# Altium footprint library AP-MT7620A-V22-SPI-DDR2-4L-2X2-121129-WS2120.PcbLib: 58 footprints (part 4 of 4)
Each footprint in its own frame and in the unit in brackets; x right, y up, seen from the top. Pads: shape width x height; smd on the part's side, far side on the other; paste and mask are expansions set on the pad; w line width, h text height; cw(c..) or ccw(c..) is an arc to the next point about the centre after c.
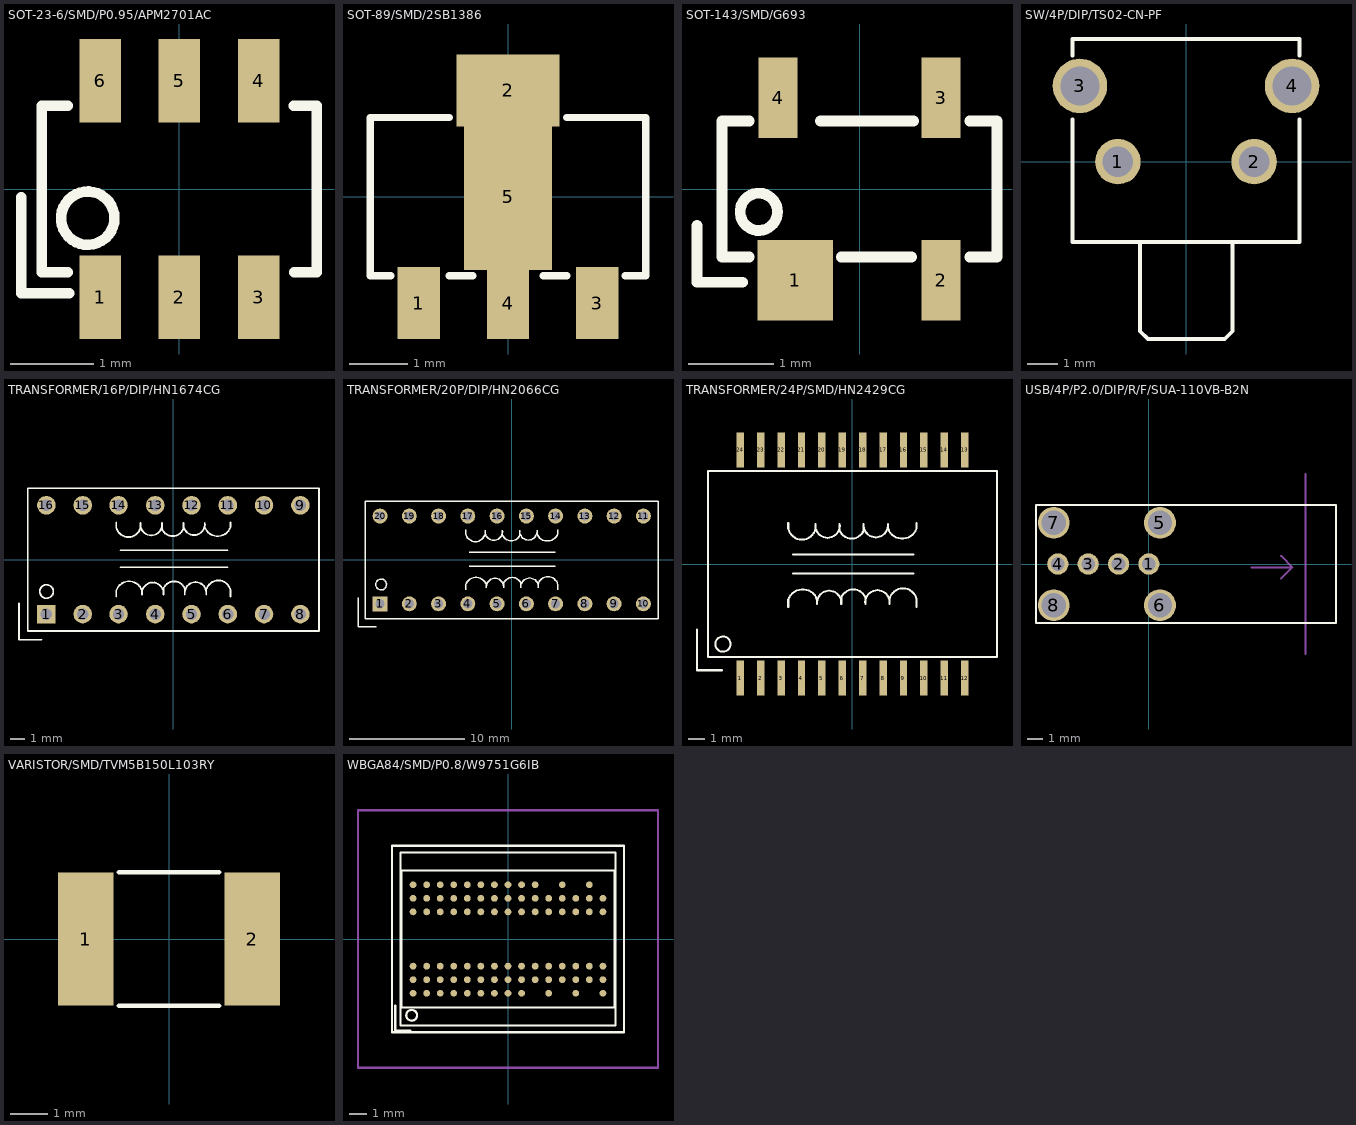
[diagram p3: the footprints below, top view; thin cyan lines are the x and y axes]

## SOT-23-6/SMD/P0.95/APM2701AC [mm]
pads (6):
  rect 0.5x1 smd: 1(-0.95,-1.3) 2(0,-1.3) 3(0.95,-1.3) 4(0.95,1.3) 5(0,1.3) 6(-0.95,1.3)
Top Overlay:
  circle w0.127: c-1.1,-0.35 r0.32
  lines w0.127: -1.9,-0.1 -1.9,-1.25 -1.32,-1.25 ; -1.34,-1 -1.65,-1 -1.65,1 -1.34,1 ; 1.37,1 1.65,1 1.65,-1 1.38,-1

## SOT-89/SMD/2SB1386 [mm]
pads (5):
  rect 0.72x1.225 smd: 1(-1.52,-1.813) 3(1.52,-1.813) 4(0,-1.813)
  rect 1.75x1.225 smd: 2(0,1.813)
  rect 1.5x2.5 smd: 5(0,0)
Top Overlay:
  lines w0.127: -2,-1.35 -2.35,-1.35 -2.35,1.35 -1,1.35 ; -1,-1.35 -0.6,-1.35 ; 0.6,-1.35 1,-1.35 ; 1,1.35 2.35,1.35 2.35,-1.35 2,-1.35

## SOT-143/SMD/G693 [mm]
pads (4):
  rect 0.89x0.95 smd: 1(-0.76,-1.075)
  rect 0.46x0.95 smd: 2(0.96,-1.075) 3(0.96,1.075) 4(-0.96,1.075)
Top Overlay:
  circle w0.127: c-1.187,-0.269 r0.22
  lines w0.127: -1.916,-0.432 -1.916,-1.1 -1.381,-1.1 ; -1.3,-0.8 -1.62,-0.8 -1.62,0.8 -1.3,0.8 ; -0.46,0.8 0.635,0.8 ; -0.216,-0.8 0.611,-0.8 ; 1.3,-0.8 1.62,-0.8 1.62,0.8 1.3,0.8

## SW/4P/DIP/TS02-CN-PF [mm]
pads (4):
  round 1.5 hole 1: 1(-2.25,0) 2(2.25,0)
  round 1.8 hole 1.3: 3(-3.5,2.5) 4(3.5,2.5)
Top Overlay:
  lines w0.127: -3.75,1.4 -3.75,-2.65 3.75,-2.65 3.75,1.4 ; -3.75,3.5 -3.75,4.05 3.75,4.05 3.75,3.5 ; -1.514,-2.677 -1.514,-5.598 -1.26,-5.852 1.28,-5.852 1.534,-5.598 1.534,-2.677

## TRANSFORMER/16P/DIP/HN1674CG [mm]
pads (16):
  rect 1.3x1.3 / inner round 1.3 / far side round 1.3 hole 0.8: 1(-8.9,-3.81)
  round 1.3 hole 0.8: 2(-6.35,-3.81) 3(-3.843,-3.81) 4(-1.27,-3.81) 5(1.27,-3.81) 6(3.81,-3.81) 7(6.35,-3.81) 8(8.9,-3.81) 9(8.9,3.81) 10(6.35,3.81) 11(3.81,3.81) 12(1.27,3.81) 13(-1.27,3.81) 14(-3.843,3.81) 15(-6.35,3.81) 16(-8.9,3.81)
Top Overlay:
  circle w0.127: c-8.885,-2.228 r0.473
  lines w0.127: -10.815,-3.076 -10.815,-5.606 -9.245,-5.606 ; -4,-2.603 -4,-2.162 ; -4,-2.162 cw(c-3.1,-2.462) -2.2,-2.161 ; -4,2.603 -4,2.263 ccw(c-3.15,2.453) -2.3,2.263 -2.3,2.564 ccw(c-1.55,2.454) -0.8,2.564 -0.8,2.164 ; -3.7,-0.536 3.8,-0.536 ; -3.7,0.663 3.8,0.663 ; -2.2,-2.162 -2.2,-2.437 cw(c-1.45,-2.354) -0.7,-2.436 -0.7,-2.037 cw(c0.05,-2.327) 0.8,-2.036 ; -0.8,2.163 ccw(c-0.05,2.454) 0.7,2.164 0.7,2.564 ccw(c1.45,2.481) 2.2,2.563 2.2,2.289 ccw(c3.1,2.59) 4,2.289 4,2.603 ; 0.8,-2.037 0.8,-2.437 cw(c1.55,-2.327) 2.3,-2.437 2.3,-2.136 cw(c3.15,-2.326) 4,-2.136 4,-2.603 ; -10.2,-5 10.2,-5 10.2,5 -10.2,5 -10.2,-5

## TRANSFORMER/20P/DIP/HN2066CG [mm]
pads (20):
  rect 1.3x1.3 / inner round 1.3 / far side round 1.3 hole 0.8: 1(-11.43,-3.81)
  round 1.3 hole 0.8: 2(-8.89,-3.81) 3(-6.35,-3.81) 4(-3.81,-3.81) 5(-1.27,-3.81) 6(1.27,-3.81) 7(3.81,-3.81) 8(6.35,-3.81) 9(8.89,-3.81) 10(11.43,-3.81) 11(11.43,3.81) 12(8.89,3.81) 13(6.35,3.81) 14(3.81,3.81) 15(1.27,3.81) 16(-1.27,3.81) 17(-3.81,3.81) 18(-6.35,3.81) 19(-8.89,3.81) 20(-11.43,3.81)
Top Overlay:
  circle w0.127: c-11.336,-2.131 r0.473
  lines w0.127: -13.343,-3.279 -13.343,-5.809 -11.773,-5.809 ; -4,-2.603 -4,-2.162 ; -4,-2.162 cw(c-3.1,-2.462) -2.2,-2.161 ; -4,2.603 -4,2.263 ccw(c-3.15,2.453) -2.3,2.263 -2.3,2.564 ccw(c-1.55,2.454) -0.8,2.564 -0.8,2.164 ; -3.7,-0.536 3.8,-0.536 ; -3.7,0.663 3.8,0.663 ; -2.2,-2.162 -2.2,-2.437 cw(c-1.45,-2.354) -0.7,-2.436 -0.7,-2.037 cw(c0.05,-2.327) 0.8,-2.036 ; -0.8,2.163 ccw(c-0.05,2.454) 0.7,2.164 0.7,2.564 ccw(c1.45,2.481) 2.2,2.563 2.2,2.289 ccw(c3.1,2.59) 4,2.289 4,2.603 ; 0.8,-2.037 0.8,-2.437 cw(c1.55,-2.327) 2.3,-2.437 2.3,-2.136 cw(c3.15,-2.326) 4,-2.136 4,-2.603 ; -12.7,-5.1 -12.7,5.1 12.7,5.1 12.7,-5.1 -12.7,-5.1

## TRANSFORMER/24P/SMD/HN2429CG [mm]
pads (24):
  rect 0.46x2.2 smd: 1(-6.985,-7.1) 2(-5.715,-7.1) 3(-4.445,-7.1) 4(-3.175,-7.1) 5(-1.905,-7.1) 6(-0.635,-7.1) 7(0.635,-7.1) 8(1.905,-7.1) 9(3.175,-7.1) 10(4.445,-7.1) 11(5.715,-7.1) 12(6.985,-7.1) 13(6.985,7.1) 14(5.715,7.1) 15(4.445,7.1) 16(3.175,7.1) 17(1.905,7.1) 18(0.635,7.1) 19(-0.635,7.1) 20(-1.905,7.1) 21(-3.175,7.1) 22(-4.445,7.1) 23(-5.715,7.1) 24(-6.985,7.1)
Top Overlay:
  circle w0.127: c-8.064,-4.991 r0.473
  lines w0.127: -9.683,-4.087 -9.683,-6.617 -8.113,-6.617 ; -4,-2.667 -4,-2.225 ; -4,-2.226 cw(c-3.1,-2.525) -2.2,-2.224 ; -4,2.54 -4,2.199 ccw(c-3.15,2.389) -2.3,2.199 -2.3,2.5 ccw(c-1.55,2.391) -0.8,2.5 -0.8,2.1 ; -3.7,-0.6 3.8,-0.6 ; -3.7,0.6 3.8,0.6 ; -2.2,-2.225 -2.2,-2.5 cw(c-1.45,-2.417) -0.7,-2.5 -0.7,-2.1 cw(c0.05,-2.39) 0.8,-2.099 ; -0.8,2.099 ccw(c-0.05,2.39) 0.7,2.101 0.7,2.5 ccw(c1.45,2.417) 2.2,2.5 2.2,2.225 ccw(c3.1,2.526) 4,2.225 4,2.54 ; 0.8,-2.1 0.8,-2.5 cw(c1.55,-2.391) 2.3,-2.5 2.3,-2.199 cw(c3.15,-2.389) 4,-2.199 4,-2.667 ; -9,-5.8 9,-5.8 9,5.8 -9,5.8 -9,-5.8

## USB/4P/P2.0/DIP/R/F/SUA-110VB-B2N [mm]
pads (8):
  round 1.4 hole 0.9: 1(0,0) 2(-2,0) 3(-4,0) 4(-6,0)
  round 2.1 hole 1.6: 5(0.73,2.72) 6(0.73,-2.72) 7(-6.27,2.72) 8(-6.27,-2.72)
Top Overlay:
  lines w0.127: -7.44,-3.9 -7.44,3.9 12.33,3.9 12.33,-3.9 -7.44,-3.9
Mechanical 16:
  lines w0.127: 6.751,-0.229 9.302,-0.229 ; 8.704,-0.962 9.452,-0.213 8.712,0.528 ; 10.33,-5.935 10.33,5.935

## VARISTOR/SMD/TVM5B150L103RY [mm]
pads (2):
  rect 1.5x3.6 smd: 1(-2.25,0) 2(2.25,0)
Top Overlay:
  lines w0.127: -1.35,-1.8 1.35,-1.8 ; -1.35,1.8 1.35,1.8

## WBGA84/SMD/P0.8/W9751G6IB [mm]
pads (84):
  round 0.4 smd: A1(-5.6,-3.2) A2(-5.6,-2.4) A3(-5.6,-1.6) A7(-5.6,1.6) A8(-5.6,2.4) A9(-5.6,3.2) B1(-4.8,-3.2) B2(-4.8,-2.4) B3(-4.8,-1.6) B7(-4.8,1.6) B8(-4.8,2.4) B9(-4.8,3.2) C1(-4,-3.2) C2(-4,-2.4) C3(-4,-1.6) C7(-4,1.6) C8(-4,2.4) C9(-4,3.2) D1(-3.2,-3.2) D2(-3.2,-2.4) D3(-3.2,-1.6) D7(-3.2,1.6) D8(-3.2,2.4) D9(-3.2,3.2) E1(-2.4,-3.2) E2(-2.4,-2.4) E3(-2.4,-1.6) E7(-2.4,1.6) E8(-2.4,2.4) E9(-2.4,3.2) F1(-1.6,-3.2) F2(-1.6,-2.4) F3(-1.6,-1.6) F7(-1.6,1.6) F8(-1.6,2.4) F9(-1.6,3.2) G1(-0.8,-3.2) G2(-0.8,-2.4) G3(-0.8,-1.6) G7(-0.8,1.6) G8(-0.8,2.4) G9(-0.8,3.2) H1(0,-3.2) H2(0,-2.4) H3(0,-1.6) H7(0,1.6) H8(0,2.4) H9(0,3.2) J1(0.8,-3.2) J2(0.8,-2.4) J3(0.8,-1.6) J7(0.8,1.6) J8(0.8,2.4) J9(0.8,3.2) K2(1.6,-2.4) K3(1.6,-1.6) K7(1.6,1.6) K8(1.6,2.4) K9(1.6,3.2) L1(2.4,-3.2) L2(2.4,-2.4) L3(2.4,-1.6) L7(2.4,1.6) L8(2.4,2.4) M2(3.2,-2.4) M3(3.2,-1.6) M7(3.2,1.6) M8(3.2,2.4) M9(3.2,3.2) N1(4,-3.2) N2(4,-2.4) N3(4,-1.6) N7(4,1.6) N8(4,2.4) P2(4.8,-2.4) P3(4.8,-1.6) P7(4.8,1.6) P8(4.8,2.4) P9(4.8,3.2) R1(5.6,-3.2) R2(5.6,-2.4) R3(5.6,-1.6) R7(5.6,1.6) R8(5.6,2.4)
Top Overlay:
  circle w0.127: c-5.686,-4.503 r0.318
  lines w0.127: -6.65,-3.937 -6.65,-5.408 -5.771,-5.408 ; -6.85,-5.5 -6.85,5.5 6.85,5.5 6.85,-5.5 -6.85,-5.5 ; -6.35,-5.1 6.35,-5.1 6.35,5.1 -6.35,5.1 -6.35,-5.1 ; -6.3,-4.05 6.3,-4.05 6.3,4.05 -6.3,4.05 -6.3,-4.05
Mechanical 16:
  lines w0.127: -8.85,-7.6 8.85,-7.6 8.85,7.6 -8.85,7.6 -8.85,-7.6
